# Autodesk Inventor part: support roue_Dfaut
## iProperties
Created: 2007-07
Part Number: support roue_Dfaut
Document SubType Name: Modeling
Designer: EF
Density: 1 g/cm^3
Author: EF
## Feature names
1. Base1
